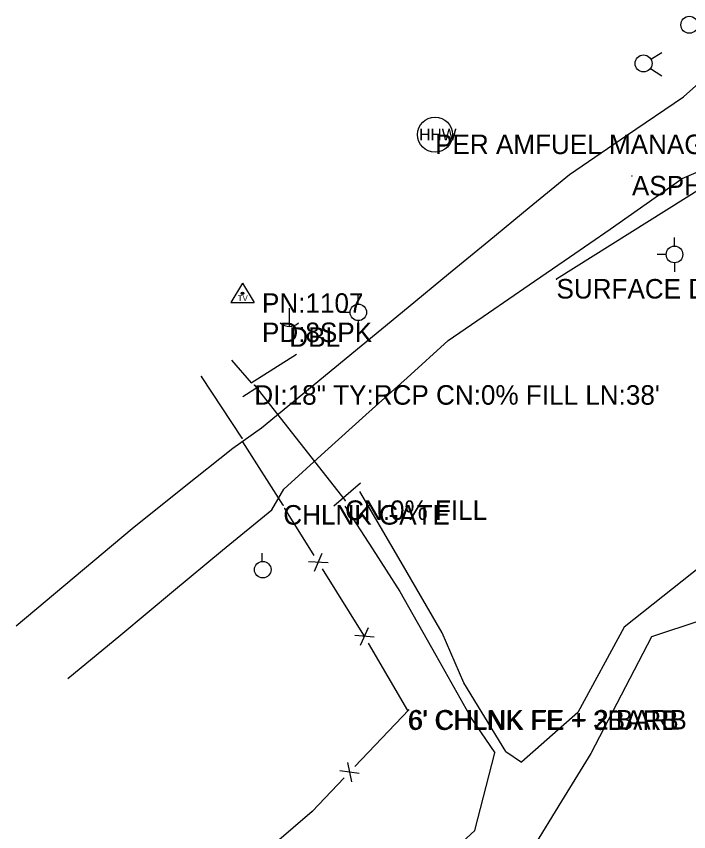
# Model space of a CAD drawing. Extents: x 929765 to 934279, y 1533086 to 1541189.
# Drawn here: x 931761.8 to 931934.2, y 1537318.7 to 1537527.5 of the extents above; entities that cross this region are included whole.
import ezdxf

# ---------------------------------------------------------------- set-up
doc = ezdxf.new("R2010")
doc.units = 0
for name, color, linetype in [('S_DITCHLINE', 7, 'Continuous'), ('S_DRG_PT_SYM', 7, 'Continuous'), ('S_DRIVEWAY', 7, 'Continuous'), ('S_FENCE', 7, 'Continuous'), ('S_FENCE_ANNOT', 7, 'Continuous'), ('S_GATE', 7, 'Continuous'), ('S_GATE_ANNOT', 7, 'Continuous'), ('S_HEADWALL', 7, 'Continuous'), ('S_HIST_HIGH_WATER', 7, 'Continuous'), ('S_HIST_HIGH_WATER_ANNOT', 7, 'Continuous'), ('S_MSC_PT_SYM', 7, 'Continuous'), ('S_SANITARY_SEWER', 7, 'Continuous'), ('S_SANITARY_SEWER_ANNOT', 7, 'Continuous'), ('S_SECONDARY_CTL', 7, 'Continuous'), ('S_SECONDARY_CTL_ANNOT', 7, 'Continuous'), ('S_SIDE_DRAIN', 7, 'Continuous'), ('S_SIDE_DRAIN_ANNOT', 7, 'Continuous'), ('S_SURVEY_TEXT_ANNOT', 7, 'Continuous'), ('S_UTILITY_POLE', 7, 'Continuous'), ('S_UTILITY_POLE_ANNOT', 7, 'Continuous'), ('S_UTL_PT_SYM', 7, 'Continuous'), ('S_WATER_UTILITIES', 7, 'Continuous')]:
    doc.layers.add(name, color=color, linetype=linetype)

msp = doc.modelspace()

# ---------------------------------------------------------------- linework, layer by layer
at = {"layer": 'S_DITCHLINE'}
for points in [[(931960.73, 1537473.11), (931955.67, 1537459.62), (931950.61, 1537446.13), (931951.63, 1537422.85), (931946.42, 1537416.45), (931944.44, 1537403.55), (931942.46, 1537390.65), (931930.06, 1537380.86), (931917.67, 1537371.06), (931905.8, 1537349.22), (931891.3, 1537336.47)], [(931964.13, 1537470.78), (931958.69, 1537458.85), (931953.25, 1537446.93), (931956.11, 1537425.64), (931962.3, 1537423.93), (931964.69, 1537424.11), (931966.9, 1537401.27), (931969.1, 1537378.44), (931958.88, 1537373.67), (931949.96, 1537376.9), (931937.32, 1537372.75), (931924.68, 1537368.59), (931916.88, 1537353.63), (931909.08, 1537338.66), (931901.6, 1537326.5), (931894.11, 1537314.34), (931873.82, 1537300.85), (931853.53, 1537287.36), (931835.12, 1537272.97), (931824.41, 1537264.81), (931813.7, 1537256.65), (931802.99, 1537248.49), (931792.29, 1537240.33), (931772.04, 1537229.23)], [(931816.99, 1537439.47), (931821.97, 1537433.62), (931833.59, 1537440.97)], [(931887.28, 1537339.17), (931876.54, 1537356.8), (931870.97, 1537369.63), (931860.44, 1537387.7), (931849.91, 1537405.77)], [(931846.02, 1537402.02), (931853.08, 1537391.12), (931860.15, 1537380.22), (931869.37, 1537363.87), (931878.59, 1537347.51), (931884.5, 1537338.85)], [(931879.34, 1537318.94), (931884.5, 1537338.85)], [(931887.28, 1537339.17), (931891.3, 1537336.47)], [(931879.34, 1537318.94), (931869.65, 1537310.02), (931859.97, 1537301.1), (931843.4, 1537290.91), (931826.83, 1537280.71), (931815.38, 1537271.41), (931803.92, 1537262.12), (931792.47, 1537252.82), (931781.02, 1537243.53), (931766.83, 1537234.17)]]:
    msp.add_lwpolyline(points, dxfattribs=at)
at = {"layer": 'S_DRG_PT_SYM'}
for points in [[(931822.82, 1537433.04), (931822.82, 1537433.09), (931822.82, 1537433.04), (931822.77, 1537433.04), (931822.82, 1537433.04), (931822.82, 1537432.99), (931822.82, 1537433.04), (931822.87, 1537433.04)], [(931846.1, 1537403.52), (931846.1, 1537403.57), (931846.1, 1537403.52), (931846.05, 1537403.52), (931846.1, 1537403.52), (931846.1, 1537403.47), (931846.1, 1537403.52), (931846.15, 1537403.52)]]:
    msp.add_lwpolyline(points, dxfattribs=at)
at = {"layer": 'S_DRIVEWAY'}
for points in [[(931932.85, 1537506.93), (931942.95, 1537515.91), (931953.05, 1537524.89)], [(931761.78, 1537371.41), (931776.64, 1537383.89), (931791.51, 1537396.36), (931804.39, 1537406.64), (931817.27, 1537416.91), (931824.65, 1537422.12), (931843.47, 1537437.59), (931862.29, 1537453.05), (931872.62, 1537461.55), (931882.95, 1537470.04), (931893.28, 1537478.54), (931903.6, 1537487.03), (931918.23, 1537496.98), (931932.85, 1537506.93)], [(931932.55, 1537485.99), (931947.12, 1537492.26), (931961.69, 1537498.53)], [(931775.03, 1537357.86), (931788.58, 1537369.12), (931802.13, 1537380.39), (931814.69, 1537390.75), (931827.26, 1537401.11), (931830.36, 1537406.42), (931840.9, 1537415.93), (931851.44, 1537425.45), (931861.97, 1537434.96), (931872.51, 1537444.48), (931882.89, 1537451.6), (931893.28, 1537458.73), (931903.66, 1537465.85), (931914.05, 1537472.98), (931932.55, 1537485.99)]]:
    msp.add_lwpolyline(points, dxfattribs=at)
at = {"layer": 'S_FENCE'}
for p, q in [((931838.24, 1537385.38), (931840.2, 1537389.98)), ((931838.24, 1537385.38), (931840.2, 1537389.98)), ((931841.72, 1537387.55), (931836.72, 1537387.81)), ((931841.72, 1537387.55), (931836.72, 1537387.81)), ((931850, 1537366.44), (931852.09, 1537370.99)), ((931850, 1537366.44), (931852.09, 1537370.99)), ((931853.54, 1537368.51), (931848.56, 1537368.92)), ((931853.54, 1537368.51), (931848.56, 1537368.92)), ((931846.73, 1537336.35), (931847.72, 1537331.45)), ((931846.73, 1537336.35), (931847.72, 1537331.45)), ((931849.69, 1537333.53), (931844.75, 1537334.27)), ((931849.69, 1537333.53), (931844.75, 1537334.27))]:
    msp.add_line(p, q, dxfattribs=at)
for points in [[(931819.7, 1537419.48), (931809.25, 1537435.27)], [(931819.7, 1537419.48), (931809.25, 1537435.27)], [(931838.16, 1537389.38), (931830.6, 1537401.49)], [(931838.16, 1537389.38), (931830.6, 1537401.49)], [(931850.87, 1537369.02), (931840.28, 1537385.99)], [(931850.87, 1537369.02), (931840.28, 1537385.99)], [(931862.14, 1537349.72), (931852.06, 1537366.99)], [(931862.14, 1537349.72), (931852.06, 1537366.99)], [(931862.39, 1537349.83), (931848.6, 1537335.35)], [(931862.39, 1537349.83), (931848.6, 1537335.35)], [(931845.84, 1537332.45), (931837.62, 1537323.81)], [(931845.84, 1537332.45), (931837.62, 1537323.81)], [(931837.62, 1537323.81), (931822.43, 1537310.8)], [(931837.62, 1537323.81), (931822.43, 1537310.8)]]:
    msp.add_lwpolyline(points, dxfattribs=at)
at = {"layer": 'S_GATE'}
msp.add_line((931830.25, 1537402.32), (931819.84, 1537418.5), dxfattribs=at)
at = {"layer": 'S_HEADWALL'}
for points in [[(931819.83, 1537430.1), (931823.87, 1537432.74)], [(931843.22, 1537402.13), (931850.04, 1537408.05)]]:
    msp.add_lwpolyline(points, dxfattribs=at)
at = {"layer": 'S_HIST_HIGH_WATER'}
msp.add_circle((931869.17, 1537497.24), 4.5, dxfattribs=at)
at = {"layer": 'S_MSC_PT_SYM'}
for points in [[(931919.64, 1537486.65), (931919.64, 1537486.7), (931919.64, 1537486.65), (931919.59, 1537486.65), (931919.64, 1537486.65), (931919.64, 1537486.6), (931919.64, 1537486.65), (931919.69, 1537486.65)], [(931809.25, 1537435.27), (931809.25, 1537435.32), (931809.25, 1537435.27), (931809.2, 1537435.27), (931809.25, 1537435.27), (931809.25, 1537435.22), (931809.25, 1537435.27), (931809.3, 1537435.27)], [(931819.7, 1537419.48), (931819.7, 1537419.53), (931819.7, 1537419.48), (931819.65, 1537419.48), (931819.7, 1537419.48), (931819.7, 1537419.43), (931819.7, 1537419.48), (931819.75, 1537419.48)], [(931819.84, 1537418.5), (931819.84, 1537418.55), (931819.84, 1537418.5), (931819.79, 1537418.5), (931819.84, 1537418.5), (931819.84, 1537418.45), (931819.84, 1537418.5), (931819.89, 1537418.5)], [(931830.25, 1537402.32), (931830.25, 1537402.37), (931830.25, 1537402.32), (931830.2, 1537402.32), (931830.25, 1537402.32), (931830.25, 1537402.27), (931830.25, 1537402.32), (931830.3, 1537402.32)], [(931830.6, 1537401.49), (931830.6, 1537401.54), (931830.6, 1537401.49), (931830.55, 1537401.49), (931830.6, 1537401.49), (931830.6, 1537401.44), (931830.6, 1537401.49), (931830.65, 1537401.49)], [(931850.87, 1537369.02), (931850.87, 1537369.07), (931850.87, 1537369.02), (931850.82, 1537369.02), (931850.87, 1537369.02), (931850.87, 1537368.97), (931850.87, 1537369.02), (931850.92, 1537369.02)], [(931862.14, 1537349.72), (931862.14, 1537349.77), (931862.14, 1537349.72), (931862.09, 1537349.72), (931862.14, 1537349.72), (931862.14, 1537349.67), (931862.14, 1537349.72), (931862.19, 1537349.72)], [(931862.39, 1537349.83), (931862.39, 1537349.88), (931862.39, 1537349.83), (931862.34, 1537349.83), (931862.39, 1537349.83), (931862.39, 1537349.78), (931862.39, 1537349.83), (931862.44, 1537349.83)], [(931837.62, 1537323.81), (931837.62, 1537323.86), (931837.62, 1537323.81), (931837.57, 1537323.81), (931837.62, 1537323.81), (931837.62, 1537323.76), (931837.62, 1537323.81), (931837.67, 1537323.81)]]:
    msp.add_lwpolyline(points, dxfattribs=at)
at = {"layer": 'S_SANITARY_SEWER'}
msp.add_line((931937.87, 1537483.79), (931900.29, 1537460.24), dxfattribs=at)
at = {"layer": 'S_SECONDARY_CTL'}
for p, q in [((931819.78, 1537459.19), (931816.77, 1537454.24)), ((931819.78, 1537459.19), (931822.73, 1537454.24)), ((931816.77, 1537454.24), (931822.73, 1537454.24))]:
    msp.add_line(p, q, dxfattribs=at)
for radius in [0.311, 0.183, 0.103]:
    msp.add_circle((931819.78, 1537456.58), radius, dxfattribs=at)
at = {"layer": 'S_SIDE_DRAIN'}
msp.add_line((931822.82, 1537433.04), (931846.1, 1537403.52), dxfattribs=at)
at = {"layer": 'S_UTILITY_POLE'}
for p, q in [((931930.54, 1537468.64), (931930.54, 1537470.89)), ((931928.45, 1537466.51), (931926.13, 1537466.51)), ((931930.62, 1537462.09), (931930.62, 1537464.42)), ((931849.47, 1537453.81), (931849.47, 1537456.06)), ((931831.77, 1537452.81), (931831.77, 1537448.09)), ((931847.38, 1537451.68), (931845.06, 1537451.68)), ((931849.55, 1537447.26), (931849.55, 1537449.58)), ((931824.86, 1537387.92), (931824.86, 1537390.03))]:
    msp.add_line(p, q, dxfattribs=at)
for centre in [(931930.55, 1537466.53), (931849.48, 1537451.7), (931824.98, 1537385.78)]:
    msp.add_circle(centre, 2.13, dxfattribs=at)
msp.add_arc((931831.83, 1537451.51), 3.41, 226.3972, 313.6028, dxfattribs=at)
at = {"layer": 'S_UTL_PT_SYM'}
msp.add_lwpolyline([(931900.29, 1537460.24), (931900.29, 1537460.29), (931900.29, 1537460.24), (931900.24, 1537460.24), (931900.29, 1537460.24), (931900.29, 1537460.19), (931900.29, 1537460.24), (931900.34, 1537460.24)], dxfattribs=at)
at = {"layer": 'S_WATER_UTILITIES'}
for p, q in [((931924.52, 1537516.52), (931927.34, 1537518.25)), ((931924.4, 1537514.21), (931927.3, 1537512.28))]:
    msp.add_line(p, q, dxfattribs=at)
for centre in [(931934.36, 1537525.36), (931922.62, 1537515.46)]:
    msp.add_circle(centre, 2.18, dxfattribs=at)

# ---------------------------------------------------------------- texts
at = {"layer": 'S_FENCE_ANNOT'}
for s, p in [("6' CHLNK FE + 3BARB", (931862.14, 1537344.72)), ("6' CHLNK FE + 2 BARB", (931862.39, 1537344.83))]:
    msp.add_text(s, height=5, dxfattribs=at).set_placement(p)
at = {"layer": 'S_GATE_ANNOT'}
msp.add_text('CHLNK GATE', height=5, dxfattribs=at).set_placement((931830.25, 1537397.32))
at = {"layer": 'S_HIST_HIGH_WATER'}
msp.add_text('HHW', height=3, rotation=360, dxfattribs=at).set_placement((931865.08, 1537495.74))
at = {"layer": 'S_HIST_HIGH_WATER_ANNOT'}
msp.add_text('PER AMFUEL MANAGER ELEV:275.67', height=5, dxfattribs=at).set_placement((931869.17, 1537492.24))
at = {"layer": 'S_SANITARY_SEWER_ANNOT'}
msp.add_text('SURFACE DIR ONLY', height=5, dxfattribs=at).set_placement((931900.29, 1537455.24))
at = {"layer": 'S_SECONDARY_CTL'}
msp.add_text('TV', height=1.5, rotation=360, dxfattribs=at).set_placement((931818.57, 1537454.57))
at = {"layer": 'S_SECONDARY_CTL_ANNOT'}
for s, p in [('PN:1107', (931824.78, 1537451.58)), ('PD:8SPK', (931824.78, 1537444.08))]:
    msp.add_text(s, height=5, dxfattribs=at).set_placement(p)
at = {"layer": 'S_SIDE_DRAIN_ANNOT'}
for s, p in [('DI:18" TY:RCP CN:0% FILL LN:38\'', (931822.82, 1537428.04)), ('CN:0% FILL', (931846.1, 1537398.52))]:
    msp.add_text(s, height=5, dxfattribs=at).set_placement(p)
at = {"layer": 'S_SURVEY_TEXT_ANNOT'}
msp.add_text('ASPHALT DW TO AMFUEL', height=5, dxfattribs=at).set_placement((931919.64, 1537481.65))
at = {"layer": 'S_UTILITY_POLE_ANNOT'}
msp.add_text('DBL', height=5, dxfattribs=at).set_placement((931831.79, 1537442.87))

doc.saveas('drawing.dxf')
